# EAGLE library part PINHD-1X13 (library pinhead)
PIN HEADER
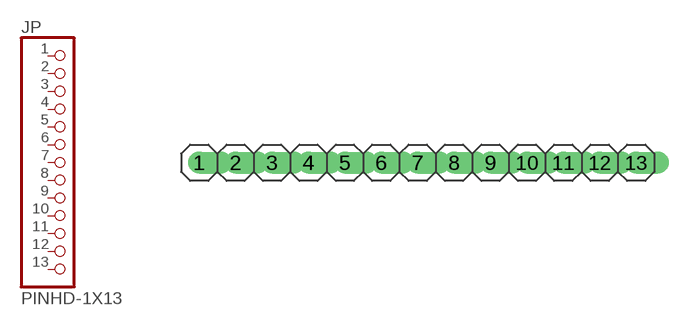
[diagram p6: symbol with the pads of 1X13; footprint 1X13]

Designator prefix JP

## PINHD-1X13  [1X13]
1  1  pas
2  2  pas
3  3  pas
4  4  pas
5  5  pas
6  6  pas
7  7  pas
8  8  pas
9  9  pas
10  10  pas
11  11  pas
12  12  pas
13  13  pas

## Footprint 1X13 (pad centres in mm)
PIN HEADER
drill 1.016 offset: 1 -15.24,0; 2 -12.7,0; 3 -10.16,0; 4 -7.62,0; 5 -5.08,0; 6 -2.54,0; 7 0,0; 8 2.54,0; 9 5.08,0; 10 7.62,0; 11 10.16,0; 12 12.7,0; 13 15.24,0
